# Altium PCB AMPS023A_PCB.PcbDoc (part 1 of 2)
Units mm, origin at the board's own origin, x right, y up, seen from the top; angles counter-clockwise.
Board outline 85 x 120 mm, 4 copper layers (Top Layer, Signal Layer 1, Signal Layer 2, Bottom Layer), stack 1.567 mm thick; 131 components, 63 nets, 410 pads, 509 vias.
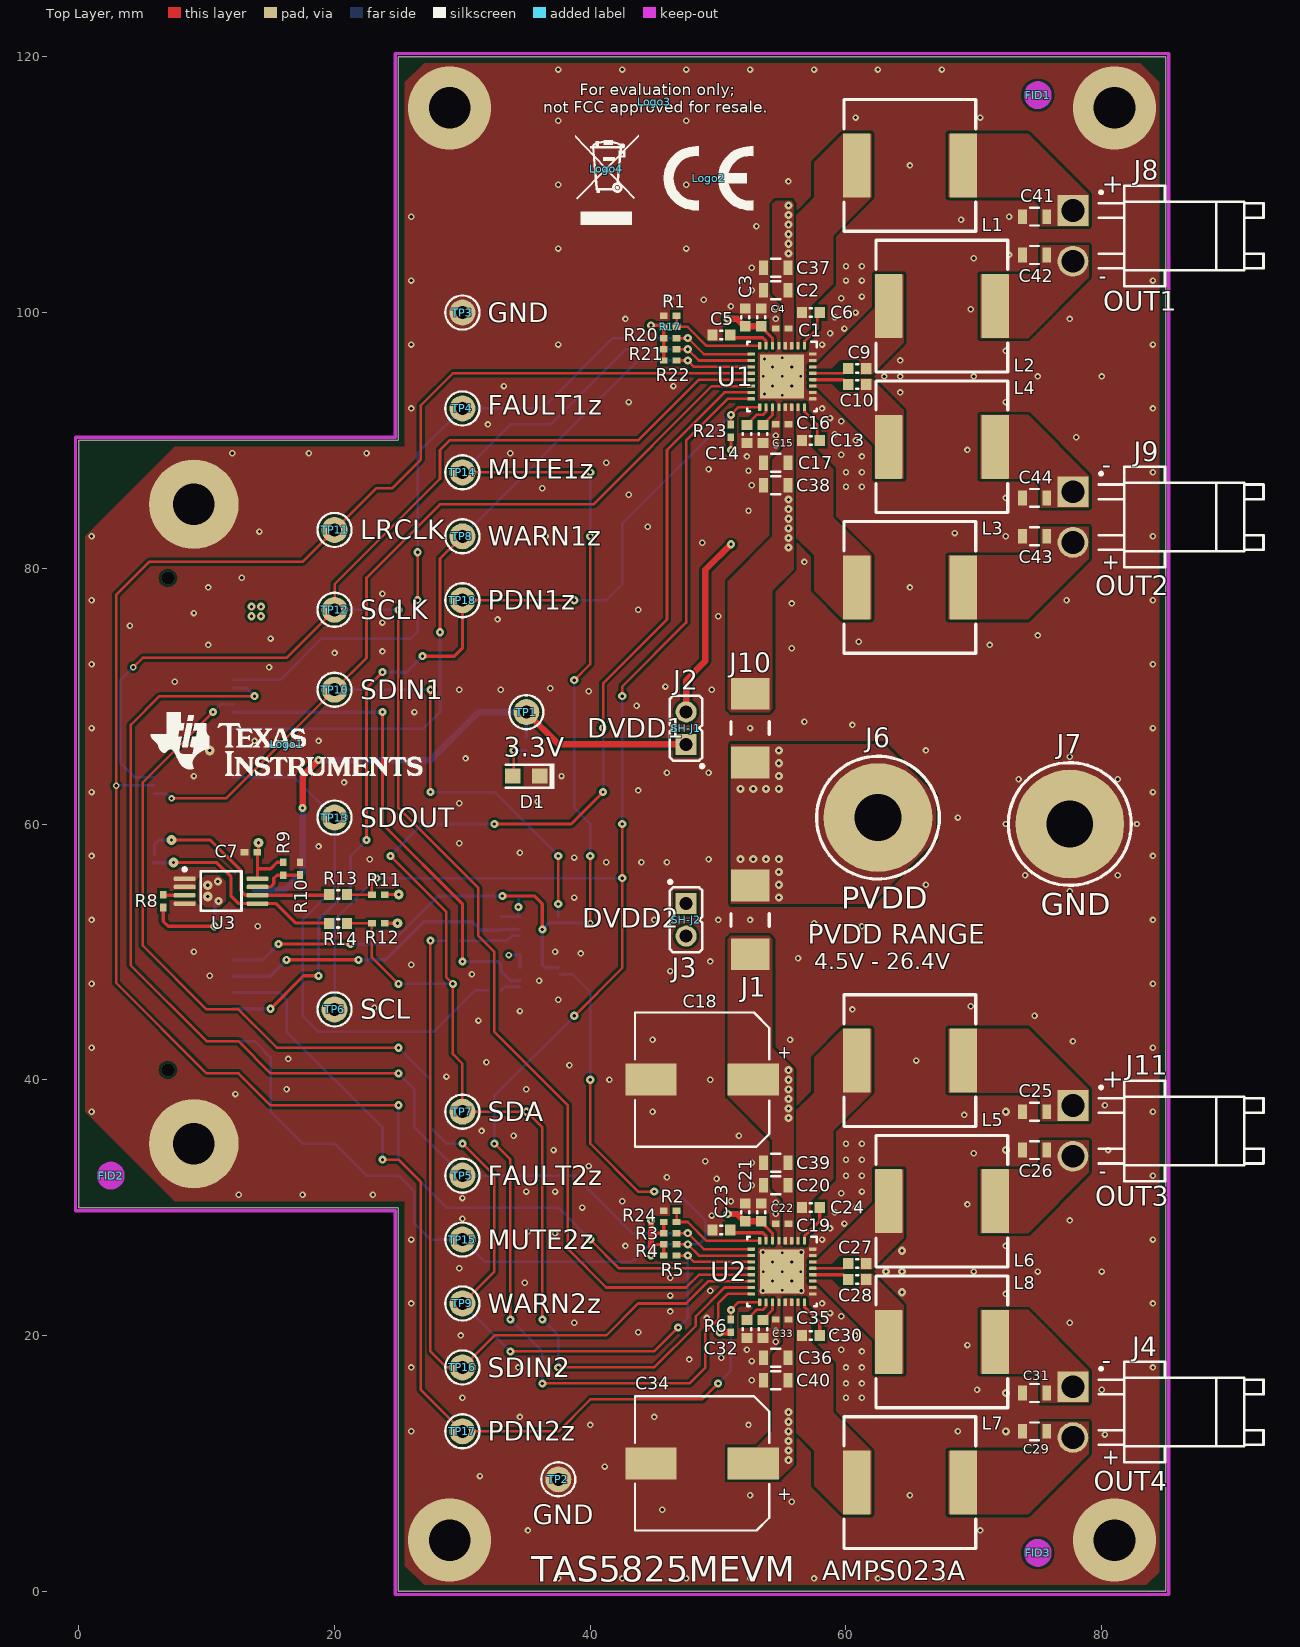
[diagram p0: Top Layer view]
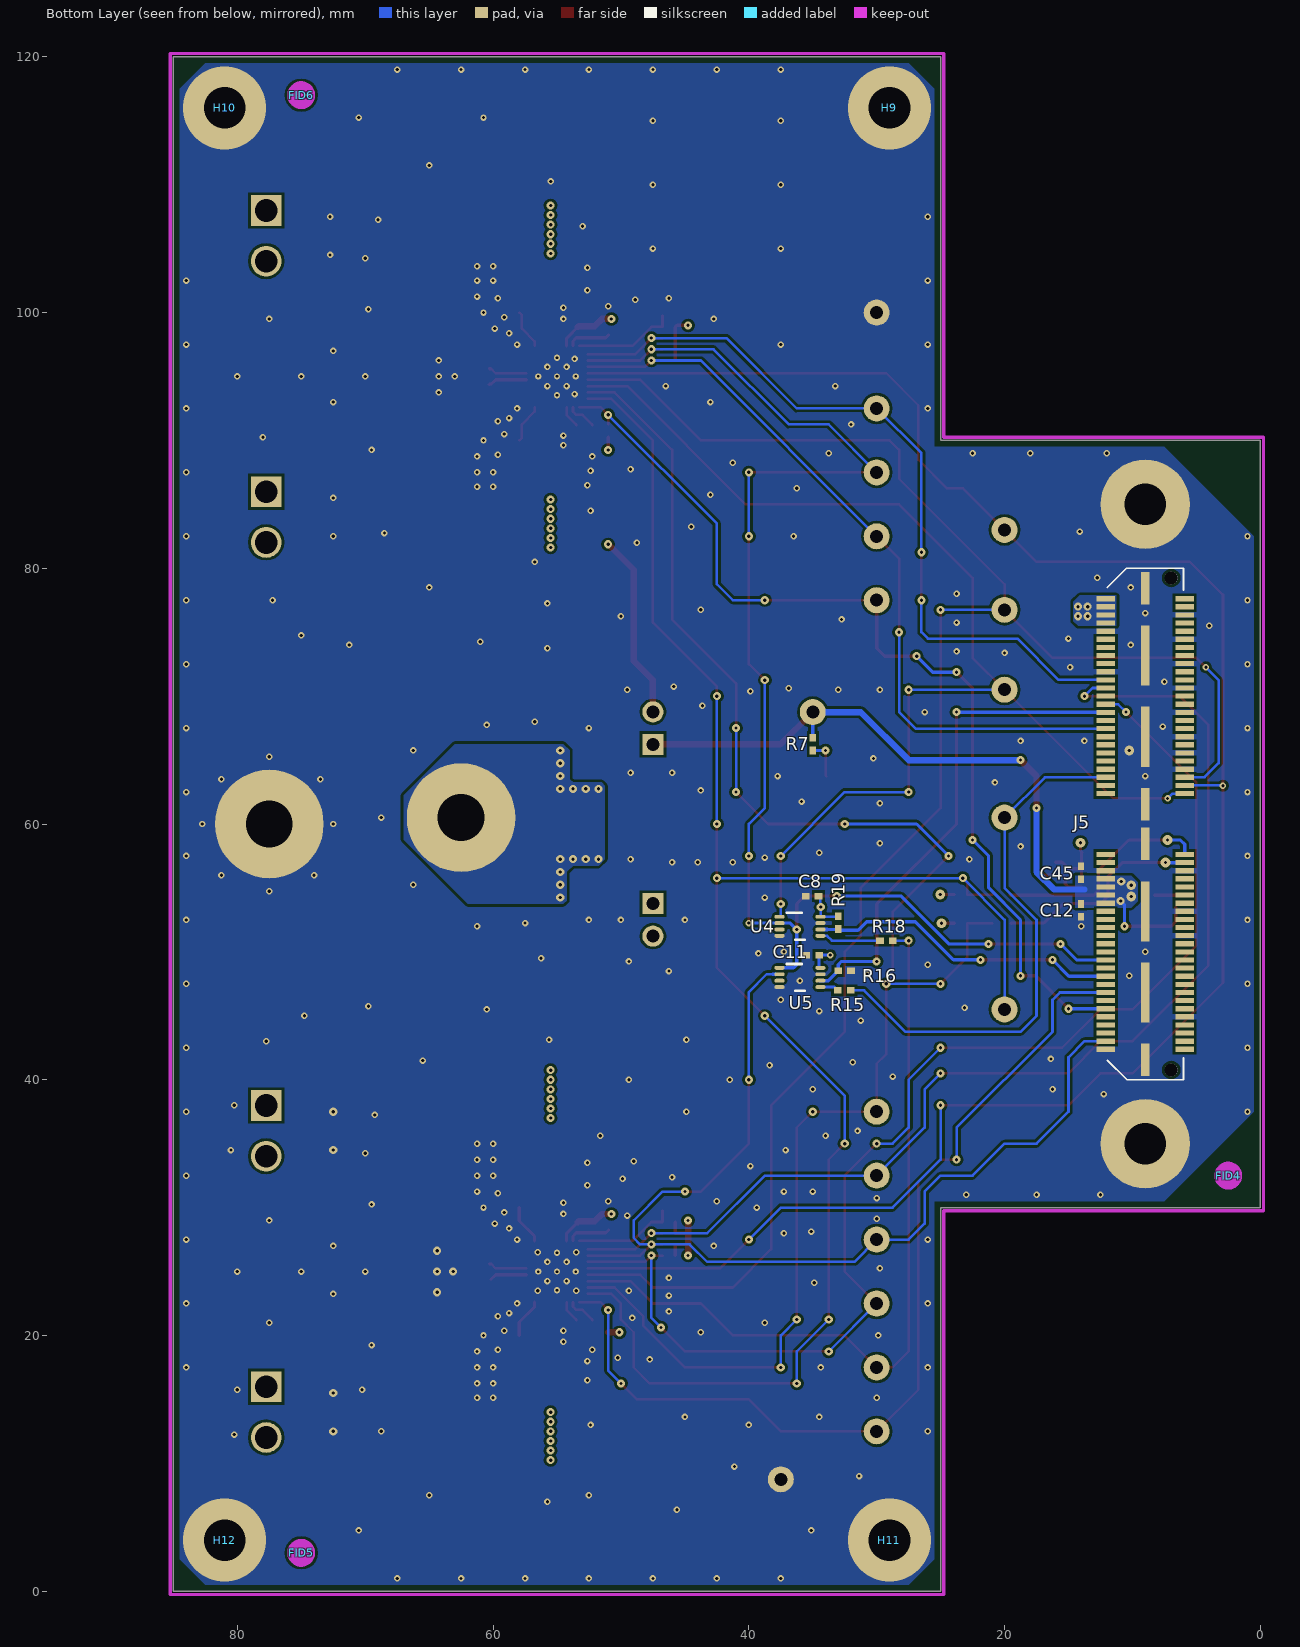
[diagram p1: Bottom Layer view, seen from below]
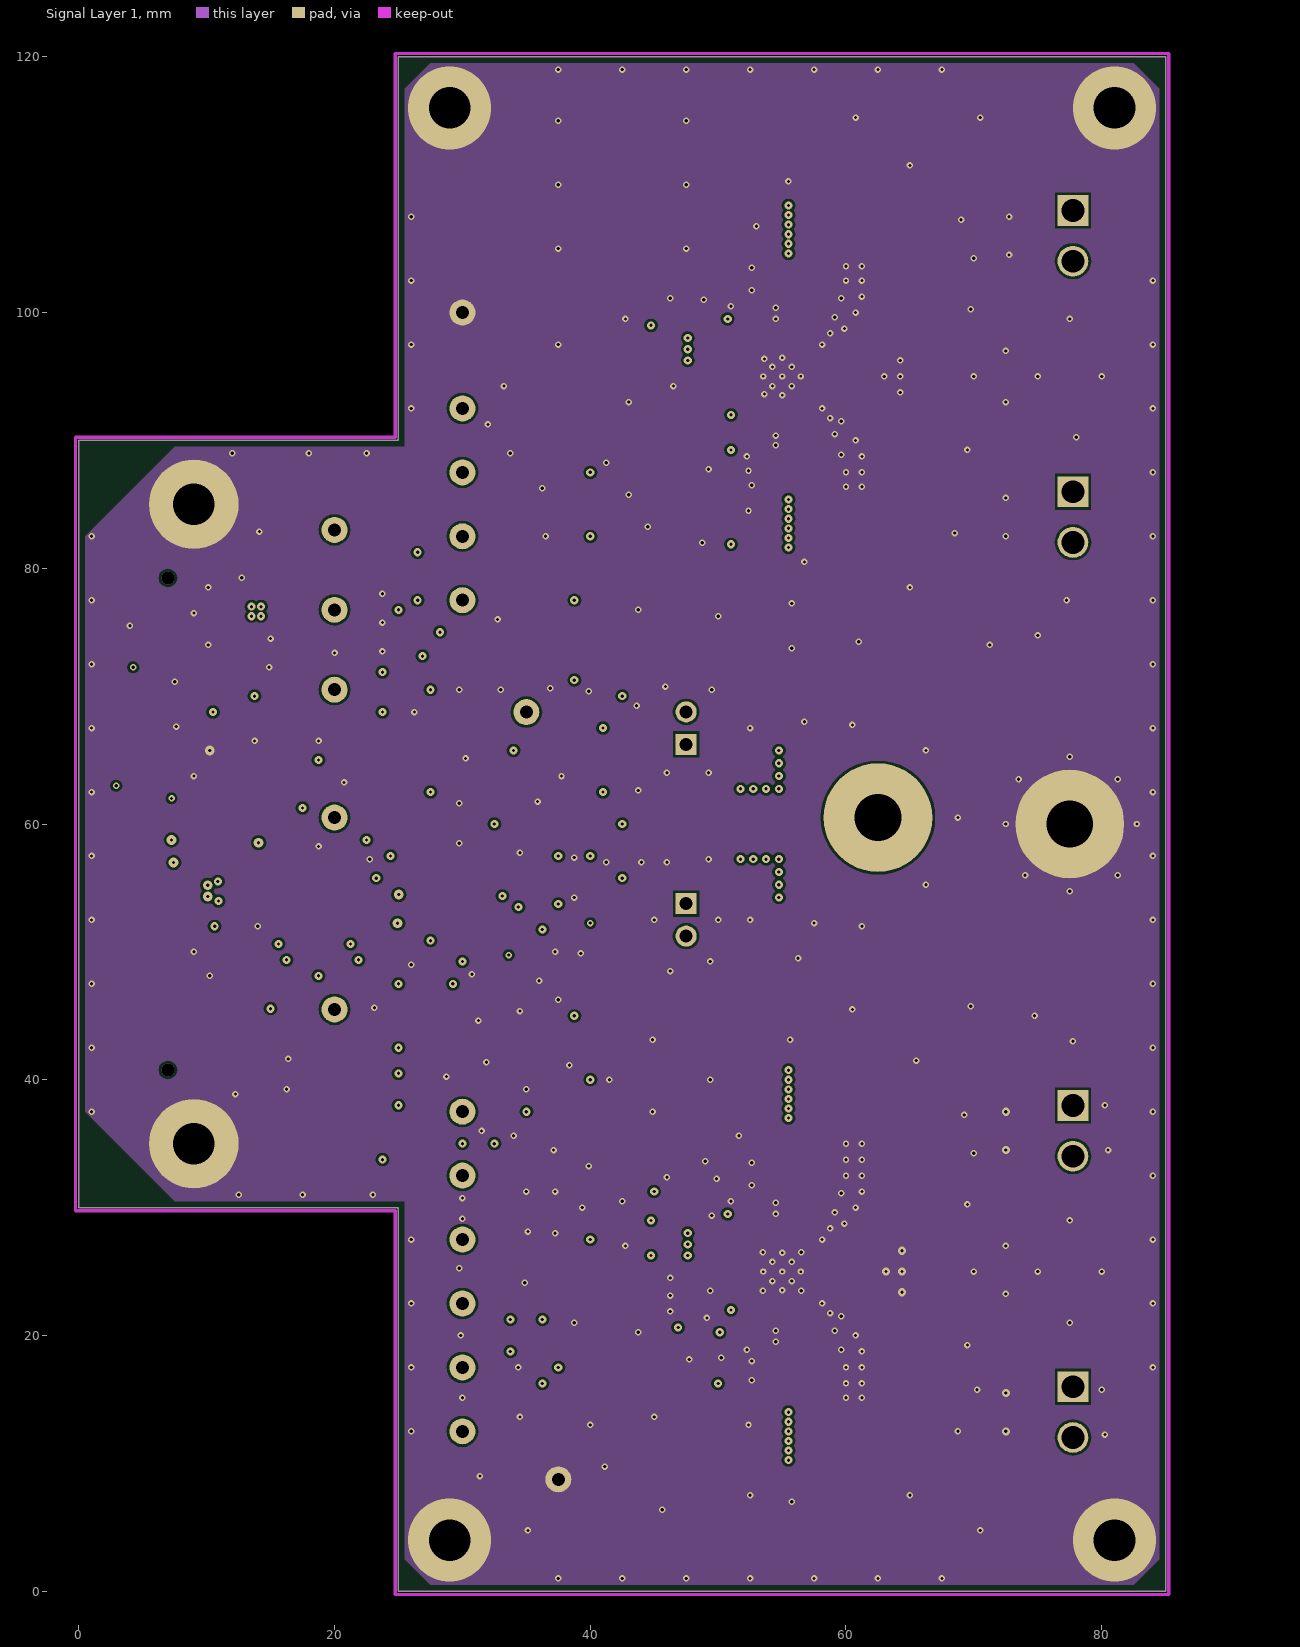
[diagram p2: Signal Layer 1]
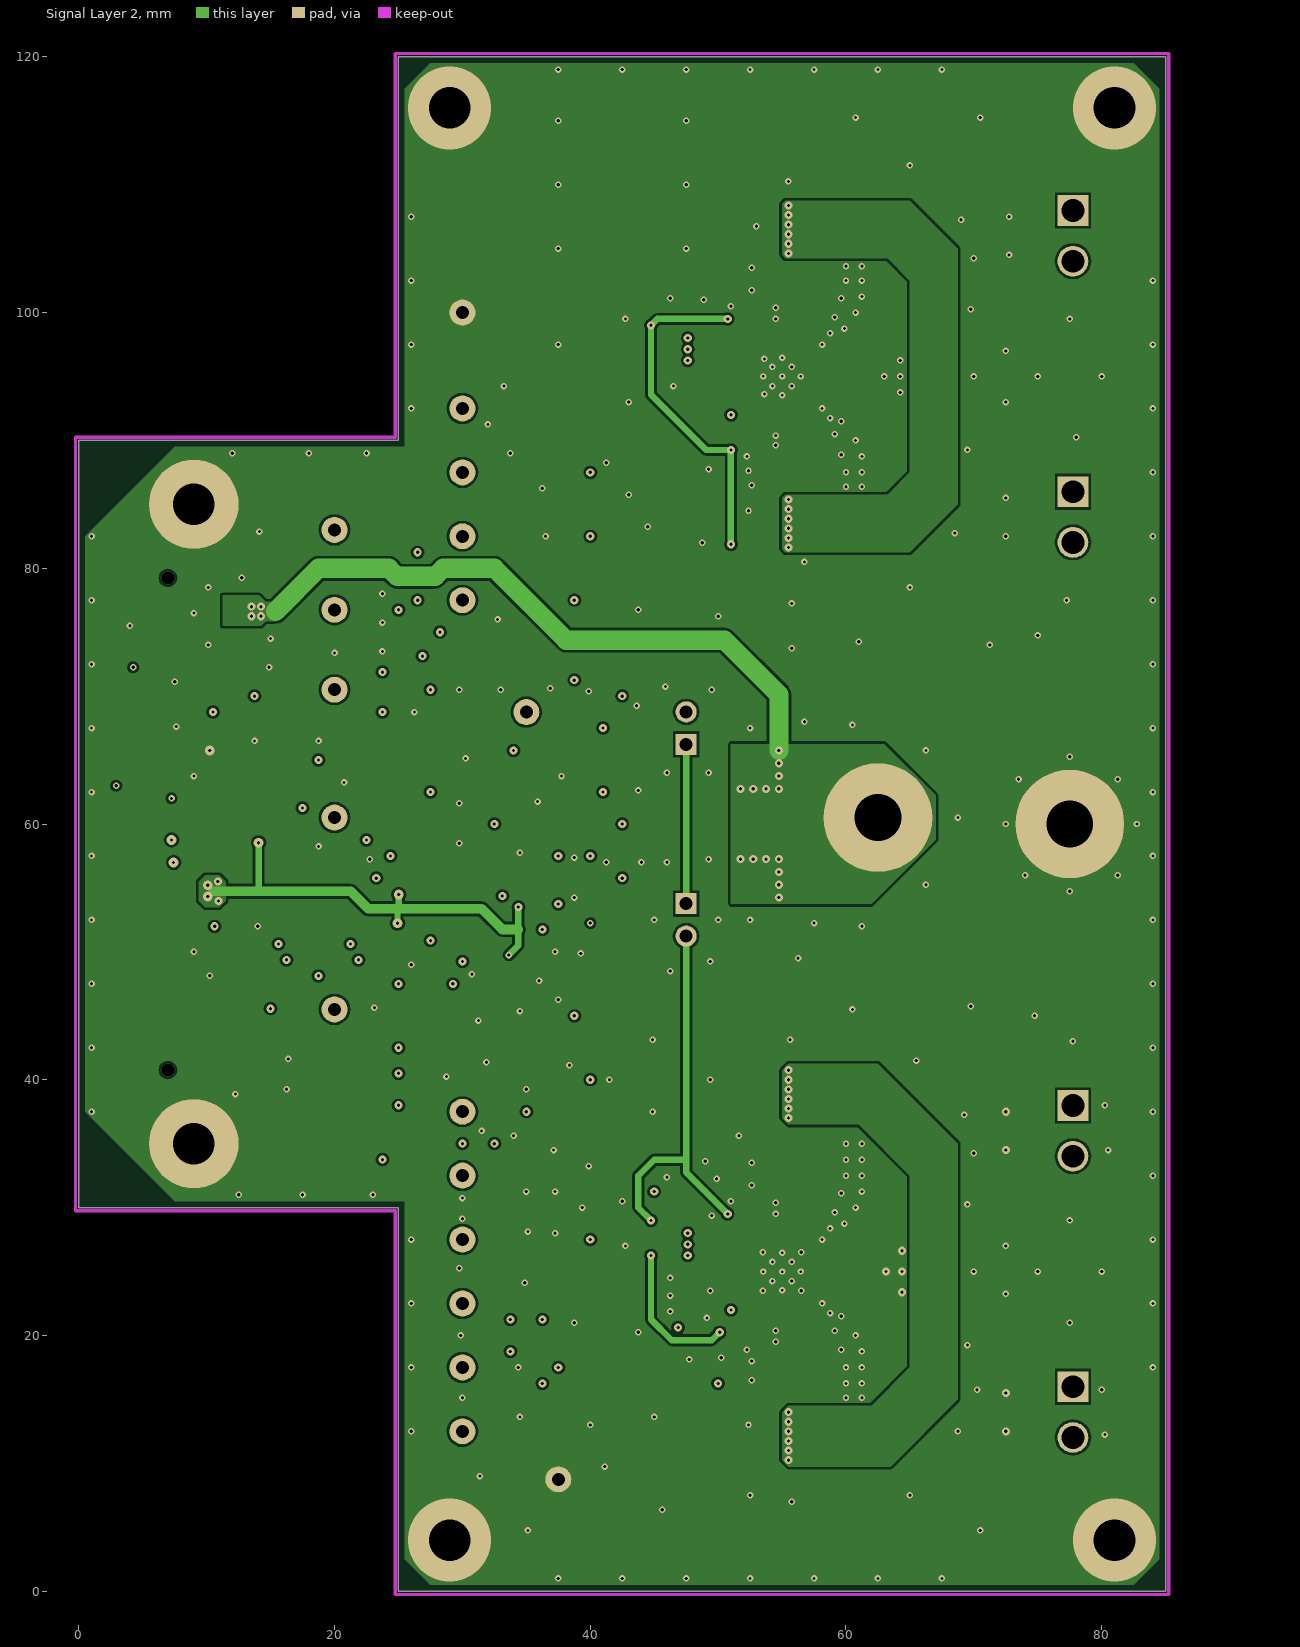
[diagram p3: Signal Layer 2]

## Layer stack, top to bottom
Top Solder: solder mask 0.0102, Solder Resist, Dk 3.5
Top Layer: signal copper 0.0696
Dielectric 1: prepreg 0.2032, FR-4, Dk 4.2
Signal Layer 1: signal copper 0.0356
Dielectric 2: core 0.9505, FR-4, Dk 4.2
Signal Layer 2: signal copper 0.0356
Dielectric 3: prepreg 0.2032, FR-4, Dk 4.2
Bottom Layer: signal copper 0.0696
Bottom Solder: solder mask 0.0102, Solder Resist, Dk 3.5

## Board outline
0,30 25,30 25,0 85,0 85,120 25,120 25,90 0,90

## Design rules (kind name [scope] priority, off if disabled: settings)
AcuteAngle [All] p1: minimum=4.50000000000000E+0001 checktracksonly=FALSE
AssemblyTestPointUsage [All] p1: valid=2
Clearance "Clearance Fiducial LibErrors" [InComponent('FID*')] p1: gap=0.2 ignorepadtopadclearanceinfootprint=TRUE except(0: Arc-SMDPad Arc-Hole Track-SMDPad Track-Hole SMDPad-Hole THPad-Hole Via-Hole Fill-Hole Poly-Hole Region-Hole Text-Hole)
Clearance Clearance_BoardEdge [OnCopper and Not InComponentClass('Logo') and not InComponentClass('FiducialMark') and not InRegion(1000,500,4000,800) and Not IsKeepout vs IsKeepOut] p2: gap=0.2 ignorepadtopadclearanceinfootprint=FALSE except(0: Arc-Hole Track-Hole SMDPad-Hole THPad-Hole Via-Hole Fill-Hole Poly-Hole Region-Hole Text-Hole)
Clearance Clearance_BoardEdge_Poly [OnCopper and InPoly vs IsKeepOut] p3: gap=0.2 ignorepadtopadclearanceinfootprint=FALSE except(0: Arc-Hole Track-Hole SMDPad-Hole THPad-Hole Via-Hole Fill-Hole Poly-Hole Region-Hole Text-Hole)
Clearance Clearance_BoardEdge_MountingHoles [OnCopper and InComponentClass('Mounting Hardware') vs IsKeepOut] p4: gap=0.2 ignorepadtopadclearanceinfootprint=FALSE except(0: Arc-Hole Track-Hole SMDPad-Hole THPad-Hole Via-Hole Fill-Hole Poly-Hole Region-Hole Text-Hole)
Clearance "Poly Clearance 3.3V" [InNamedPolygon('+3.3V_L04_P006')] p5: gap=0.2 ignorepadtopadclearanceinfootprint=FALSE except(0: Arc-Hole Track-Hole SMDPad-Hole THPad-Hole Via-Hole Fill-Hole Poly-Hole Region-Hole Text-Hole)
Clearance "Poly Clearance Outputs" [(InNet('SPK1_OUTA+') AND InNet('SPK1_OUTA-') AND InNet('SPK1_OUTB+') AND InNet('SPK1_OUTB-') AND InNet('SPK2_OUTA+') AND InNet('SPK2_OUTA-') AND InNet('SPK2_OUTB+') AND InNet('SPK2_OUTB-')) vs (InComponent('UD1') AND InComponent('UD2'))] p6: gap=0.2 ignorepadtopadclearanceinfootprint=FALSE except(0: Arc-Hole Track-Hole SMDPad-Hole THPad-Hole Via-Hole Fill-Hole Poly-Hole Region-Hole Text-Hole)
Clearance "Poly Clearance PVDD" [All] p7: gap=0.2 ignorepadtopadclearanceinfootprint=FALSE except(0: Arc-Hole Track-Hole SMDPad-Hole THPad-Hole Via-Hole Fill-Hole Poly-Hole Region-Hole Text-Hole)
Clearance Clearance_Keepouts [((IsTrack Or IsArc) And Not InPoly) And IsFree and IsKeepOut vs ((IsTrack Or IsArc) And Not InPoly) And IsFree and IsKeepOut] p8: gap=0 ignorepadtopadclearanceinfootprint=FALSE
Clearance Clearance_Poly [InPolygon] p9: gap=0.25 ignorepadtopadclearanceinfootprint=FALSE except(0: Arc-Hole Track-Hole SMDPad-Hole THPad-Hole Via-Hole Fill-Hole Poly-Hole Region-Hole Text-Hole)
Clearance [All] p10: gap=0.2 ignorepadtopadclearanceinfootprint=FALSE except(0: Arc-Hole Track-Hole SMDPad-Hole THPad-Hole Via-Hole Fill-Hole Poly-Hole Region-Hole Text-Hole)
ComponentClearance "TAS5754 Clearance" [InComponent('U2') vs InComponent('C*')] p1: gap=0.251 collisioncheckmode=3 verticalgap=0 showdistances=FALSE
ComponentClearance ComponentClearance_MountingHoles_FiducialMarks [InComponentClass('Mounting Holes') vs InComponentClass('FiducialMark')] p2: gap=1.27 collisioncheckmode=3 verticalgap=0.254 showdistances=FALSE
ComponentClearance ComponentClearance_Shunt [InComponentClass('Header') vs InComponentClass('Shunt')] p3: gap=0 collisioncheckmode=3 verticalgap=0 showdistances=FALSE
ComponentClearance ComponentClearance_Logo [InComponentClass('Logo')] p4: gap=0 collisioncheckmode=3 verticalgap=0 showdistances=FALSE
ComponentClearance ComponentClearance_ScrewToNut [(HasFootprint('NY PMS 440 0025 PH')) vs (HasFootprint('Keystone_1902C'))] p5: gap=0 collisioncheckmode=3 verticalgap=0 showdistances=FALSE
ComponentClearance ComponentClearance_MountingHoles [InComponentClass('Mounting Holes')] p6: gap=6.35 collisioncheckmode=3 verticalgap=2540 showdistances=FALSE
ComponentClearance ComponentClearance_SmallPassives [HasFootprint('0201*') or HasFootprint('0402*') or HasFootprint('0508') or HasFootprint('0603*') or HasFootprint('0612') or HasFootprint('0805*') or HasFootprint('0815*') or HasFootprint('0830*') or HasFootprint('1206*') or HasFootprint('1210*') or HasFootprint('1808*') or HasFootprint('1812*') or HasFootprint('1825*') or HasFootprint('2010*') or HasFootprint('2220*') or HasFootprint('2225*') or HasFootprint('2512*') or HasFootprint('2728*') or HasFootprint('3518*') or HasFootprint('DCU*') or HasFootprint('DEM*') or HasFootprint('HAR*') or HasFootprint('IND*') or HasFootprint('NFZ*') or HasFootprint('RHB*') or HasFootprint('SM*') vs HasFootprint('0201*') or HasFootprint('0402*') or HasFootprint('0508') or HasFootprint('0603*') or HasFootprint('0612') or HasFootprint('0805*') or HasFootprint('0815*') or HasFootprint('0830*') or HasFootprint('1206*') or HasFootprint('1210*') or HasFootprint('1808*') or HasFootprint('1812*') or HasFootprint('1825*') or HasFootprint('2010*') or HasFootprint('2220*') or HasFootprint('2225*') or HasFootprint('2512*') or HasFootprint('2728*') or HasFootprint('3518*') or HasFootprint('DCU*') or HasFootprint('DEM*') or HasFootprint('HAR*') or HasFootprint('IND*') or HasFootprint('NFZ*') or HasFootprint('RHB*') or HasFootprint('SM*')] p7: gap=0.2 collisioncheckmode=3 verticalgap=0 showdistances=FALSE
ComponentClearance ComponentClearance_THtoSMT [IsThruComponent vs IsSMTComponent] p8: gap=0 collisioncheckmode=3 verticalgap=0 showdistances=FALSE
ComponentClearance ComponentClearance_THtoTH [IsThruComponent vs IsThruComponent] p9: gap=0.25 collisioncheckmode=3 verticalgap=0 showdistances=FALSE
ComponentClearance [All] p10: gap=1.016 collisioncheckmode=3 verticalgap=0.254 showdistances=FALSE
DiffPairsRouting [All] p1: maxlimit=2.54 minlimit=0.254 mostfreqgap=0.254 toplayer_minwidth=0.381 toplayer_maxwidth=0.381 toplayer_prefwidth=0.381 midlayer1_minwidth=0.381 midlayer1_maxwidth=0.381 midlayer1_prefwidth=0.381 midlayer2_minwidth=0.381 midlayer2_maxwidth=0.381 midlayer2_prefwidth=0.381 bottomlayer_minwidth=0.381 bottomlayer_maxwidth=0.381 bottomlayer_prefwidth=0.381 maxuncoupledlength=25.4
FabricationTestPointUsage TestPointUsage [All] p1: valid=2 allowmultiple=FALSE
FabricationTestpoint Testpoint [All] p1: side=3 testpointundercomponent=TRUE minsize=1.016 maxsize=2.54 preferedsize=1.524 minholesize=0 maxholesize=1.016 preferedholesize=0.813 testpointgrid=0.025 allowsidetop=TRUE allowsidebottom=TRUE usegrid=TRUE gridtolerance=0
FanoutControl Fanout_LCC [IsLCC] p1: bgadir=Out bgaviamode=Centered fanoutstyle=Auto fanoutdirection=Alternating viagrid=0.025 // Fanout_LCC (Default Rule)
FanoutControl Fanout_BGA [IsBGA] p2: bgadir=Out bgaviamode=Centered fanoutstyle=Auto fanoutdirection=Alternating viagrid=0.025 // Fanout_BGA (Default Rule)
FanoutControl Fanout_Default [All] p4: bgadir=Out bgaviamode=Centered fanoutstyle=Auto fanoutdirection=Alternating viagrid=0.025 // Fanout_Default (Default Rule)
FanoutControl Fanout_Small [(CompPinCount < 5)] p5: bgadir=Out bgaviamode=Centered fanoutstyle=Auto fanoutdirection=OutThenIn viagrid=0.025 // Fanout_Small (Default Rule)
Height [All] p1: minheight=0 maxheight=40 prefheight=25
HoleSize [All] p1: absolutevalues=TRUE maxlimit=3.81 minlimit=0.191 maxpercent=80.000 minpercent=20.000
HoleToHoleClearance "Hole 2 Hole For Hardware" [(InComponentClass('Screw') OR InComponentClass('Standoff') OR InComponentClass('Washer')) vs (InComponentClass('Screw') OR InComponentClass('Standoff') OR InComponentClass('Washer'))] p1: gap=0 allowstackedmicrovias=TRUE
HoleToHoleClearance [All] p2: gap=0.254 allowstackedmicrovias=TRUE
MinimumAnnularRing MinimumAnnularRing_ThermalPadVias [IsVia and InAnyComponent] p1: minimumring=0.15
MinimumAnnularRing [All] p2: minimumring=0.127
MinimumSolderMaskSliver "MinSolderMaskSliver LibErrors" [(HasFootprint('DB*') or HasFootprint('DC*'))] p1: minsoldermaskwidth=0.089
MinimumSolderMaskSliver MinimumSolderMaskSliver_Logo [InComponentClass('Logo') vs InComponentClass('Logo')] p2: minsoldermaskwidth=0.018
MinimumSolderMaskSliver [All] p3: minsoldermaskwidth=0.127
PlaneConnect [All] p1: planeconnectstyle=Relief reliefexpansion=0.254 reliefentries=4 reliefconductorwidth=0.254 reliefairgap=0.254
PolygonConnect PreFlood [All] p1: connectstyle=Direct reliefconductorwidth=0.254 reliefentries=4 polygonreliefangle="90 Angle" airgapwidth=0.254
PolygonConnect "Narrow Thermals" [(InComponent('C*') OR InComponent('D*') OR InComponent('J*') OR InComponent('R*') OR InComponent('S*') OR InComponent('TP*') OR InComponent('U*')) vs InNet('GND')] p2: connectstyle=Relief reliefconductorwidth=0.2 reliefentries=4 polygonreliefangle="90 Angle" airgapwidth=0.2
PolygonConnect "Wide Thermals" [(InComponent('C1') OR InComponent('C3') OR InComponent('C5') OR InComponent('C6') OR InComponent('C137')) vs InNet('GND')] p3: connectstyle=Relief reliefconductorwidth=0.25 reliefentries=4 polygonreliefangle="90 Angle" airgapwidth=1
PolygonConnect "PostFlood GND" [(InComponent('C*') OR InComponent('J2') OR InComponent('J6') OR InComponent('J7') OR InComponent('J8') OR InComponent('U1') OR InComponent('U2')) vs InNet('GND')] p4: connectstyle=Direct reliefconductorwidth=0.254 reliefentries=4 polygonreliefangle="90 Angle" airgapwidth=0.254
PolygonConnect [All] p5: connectstyle=Relief reliefconductorwidth=0.25 reliefentries=4 polygonreliefangle="90 Angle" airgapwidth=0.75
RoutingVias ThermalPadVias [IsVia and InAnyComponent] p1: holewidth=0.2 width=0.5 viastyle="Through Hole" minholewidth=0.2 minwidth=0.5 maxholewidth=0.33 maxwidth=0.6
RoutingVias [All] p2: holewidth=0.203 width=0.711 viastyle="Through Hole" minholewidth=0.203 minwidth=0.457 maxholewidth=3.25 maxwidth=7
SilkToBoardRegionClearance [Not ((IsComment or IsDesignator) And (Hide <> 'False')) and not InRegion(1000,500,4000,800)] p1:
SilkToSilkClearance SilkToSilkClearance_Pb-FreeLogo [(HasFootprint('Pb-Free_Overlay_Medium') OR HasFootprint('Pb-Free_Overlay_Small')) vs (HasFootprint('Pb-Free_Overlay_Medium') OR HasFootprint('Pb-Free_Overlay_Small'))] p1: silktosilkclearance=0
SilkToSilkClearance [All] p2: silktosilkclearance=0.127
SilkToSolderMaskClearance "SilkToMask LibErrors" [HasFootprint('LTST*') or HasFootprint('DCU*')] p1: minsilkscreentomaskgap=0.076 clearancetoexposedcopper=FALSE
SilkToSolderMaskClearance SilkToComponentPadClearance [(IsPad or IsFill or IsRegion) and InAnycomponent] p2: minsilkscreentomaskgap=0.127 clearancetoexposedcopper=TRUE
SilkToSolderMaskClearance "Silk to Solder Mask Opening" [All] p3: minsilkscreentomaskgap=0.019 clearancetoexposedcopper=FALSE
SolderMaskExpansion [All] p1: expansion=0.05
Width [All] p1: maxlimit=5 minlimit=0.15 preferedwidth=0.25 checkconnectedcopper=TRUE
13 further rules are at their usual default settings.

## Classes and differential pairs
component class AssemblyNote: ZZ1 ZZ2 ZZ3
component class FiducialMark: FID1 FID2 FID3 FID4 FID5 FID6
component class AMPS023A_EVM_Hardware: FID1 FID2 FID3 FID4 FID5 FID6 H9 H10 H11 H12 Logo1 Logo2 Logo3 Logo4 SH-J1 SH-J2 ZZ1 ZZ2 ZZ3
component class Logo: Logo1
component class AMPS023A_BTL1: C1 C2 C3 C4 C5 C6 C9 C10 C13 C14 C15 C16 C17 C37 C38 C41 C42 C43 C44 J8 J9 L1 L2 L3 L4 R1 R17 R20 R21 R22 R23 U1
component class AMPS023A_BTL2: C18 C19 C20 C21 C22 C23 C24 C25 C26 C27 C28 C29 C30 C31 C32 C33 C34 C35 C36 C39 C40 J4 J11 L5 L6 L7 L8 R2 R3 R4 R5 R6 R24 U2
component class AMPS023A_PPCMB-IO: C7 C8 C11 C12 C45 D1 J1 J2 J3 J5 J6 J7 J10 R7 R8 R9 R10 R11 R12 R13 R14 R15 R16 R18 R19 R25 R26 R33 R35 R38 R39 R40 TP1 TP2 TP3 TP4 TP5 TP6 TP7 TP8 TP9 TP10 TP11 TP12 TP13 TP14 TP15 TP16 TP17 TP18 U3 U4 U5
component class Header: J2 J3
component class Shunt: SH-J1 SH-J2

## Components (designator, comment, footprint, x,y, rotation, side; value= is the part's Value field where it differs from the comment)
C1 "C1005X7R1H104K050BB" 0402L 55,98.75 r180 top value=0.1uF
C2 "C2012JB1V226M125AC" 0805_KTR 54.5,101.75 r0 top value=22uF
C3 "C0603C475K8PACTU" 0603L 52.125,99.625 r270 top value=4.7uF
C4 "C0603C104K4RACTU" 0603L 53.375,99.625 r90 top value=0.1uF
C5 "C0603C105K4PACTU" 0603L 50.25,98.25 r180 top value=1uF
C6 "C1608X7R1H224K080AB" 0603L 57.25,100 r180 top value=0.22uF
C7 "C1005X7R1H104K050BB" 0402L 13.462,57.784 r180 top value=0.1uF
C8 "C1005X7R1H104K050BB" 0402L 35.052,54.356 r180 bottom value=0.1uF
C9 "C1608X7R1H224K080AB" 0603L 60.875,95.625 r0 top value=0.22uF
C10 "C1608X7R1H224K080AB" 0603L 60.875,94.375 r0 top value=0.22uF
C11 "C1005X7R1H104K050BB" 0402L 35,49.75 r180 bottom value=0.1uF
C12 "C1005X7R1H104K050BB" 0402L 14.021,53.237 r90 bottom value=0.1uF
C13 "C1608X7R1H224K080AB" 0603L 57.25,90 r180 top value=0.22uF
C14 "C0603C105K4PACTU" 0603L 52.25,90.5 r270 top value=1uF
C15 "C0603C105K4PACTU" 0603L 53.5,90.5 r270 top value=1uF
C16 "C1005X7R1H104K050BB" 0402L 55,91.25 r180 top value=0.1uF
C17 "C2012JB1V226M125AC" 0805_KTR 54.5,88.25 r0 top value=22uF
C18 "+" SM_RADIAL_10BMM 48.75,40 r180 top value=390uF
C19 "C1005X7R1H104K050BB" 0402L 55,28.75 r180 top value=0.1uF
C20 "C2012JB1V226M125AC" 0805_KTR 54.5,31.75 r0 top value=22uF
C21 "C0603C475K8PACTU" 0603L 52.125,29.625 r270 top value=4.7uF
C22 "C0603C104K4RACTU" 0603L 53.375,29.625 r90 top value=0.1uF
C23 "C0603C105K4PACTU" 0603L 50.25,28.25 r180 top value=1uF
C24 "C1608X7R1H224K080AB" 0603L 57.25,30 r180 top value=0.22uF
C25 "C0805C684K5RACTU" 0805_KTR 74.75,37.5 r180 top value=0.68uF
C26 "C0805C684K5RACTU" 0805_KTR 74.75,34.5 r180 top value=0.68uF
C27 "C1608X7R1H224K080AB" 0603L 60.875,25.625 r0 top value=0.22uF
C28 "C1608X7R1H224K080AB" 0603L 60.875,24.375 r0 top value=0.22uF
C29 "C0805C684K5RACTU" 0805_KTR 74.75,12.5 r180 top value=0.68uF
C30 "C1608X7R1H224K080AB" 0603L 57.25,20 r180 top value=0.22uF
C31 "C0805C684K5RACTU" 0805_KTR 74.75,15.5 r180 top value=0.68uF
C32 "C0603C105K4PACTU" 0603L 52.25,20.5 r270 top value=1uF
C33 "C0603C105K4PACTU" 0603L 53.5,20.5 r270 top value=1uF
C34 "+" SM_RADIAL_10BMM 48.75,10 r180 top value=390uF
C35 "C1005X7R1H104K050BB" 0402L 55,21.25 r180 top value=0.1uF
C36 "C2012JB1V226M125AC" 0805_KTR 54.5,18.25 r0 top value=22uF
C37 "C2012JB1V226M125AC" 0805_KTR 54.5,103.5 r0 top value=22uF
C38 "C2012JB1V226M125AC" 0805_KTR 54.5,86.5 r0 top value=22uF
C39 "C2012JB1V226M125AC" 0805_KTR 54.5,33.5 r0 top value=22uF
C40 "C2012JB1V226M125AC" 0805_KTR 54.5,16.5 r0 top value=22uF
C41 "C0805C684K5RACTU" 0805_KTR 74.75,107.5 r180 top value=0.68uF
C42 "C0805C684K5RACTU" 0805_KTR 74.75,104.5 r180 top value=0.68uF
C43 "C0805C684K5RACTU" 0805_KTR 74.75,82.5 r180 top value=0.68uF
C44 "C0805C684K5RACTU" 0805_KTR 74.75,85.5 r180 top value=0.68uF
C45 "C1005X7R1H104K050BB" 0402L 14.021,56.184 r270 bottom value=0.1uF
D1 "3.3V" LTST-C170KGKT_Green 35,63.75 r0 top value=Green
FID1 "DNP" Fiducial6.4-20 75,117 r0 top
FID2 "DNP" Fiducial6.4-20 2.5,32.5 r0 top
FID3 "DNP" Fiducial6.4-20 75,3 r0 top
FID4 "DNP" Fiducial6.4-20 2.5,32.5 r180 bottom
FID5 "DNP" Fiducial6.4-20 75,3 r180 bottom
FID6 "DNP" Fiducial6.4-20 75,117 r180 bottom
H9 "Standoff, M3x30mm" Harwin_R30-1003002 29,116 r180 bottom
H10 "Standoff, M3x30mm" Harwin_R30-1003002 81,116 r180 bottom
H11 "Standoff, M3x30mm" Harwin_R30-1003002 29,4 r180 bottom
H12 "Standoff, M3x30mm" Harwin_R30-1003002 81,4 r180 bottom
J1 "" HARWIN_S1911-46R 52.5,52.5 r90 top
J2 "DVDD1" Sullins_PBC02SAAN 47.5,67.5 r180 top
J3 "DVDD2" Sullins_PBC02SAAN 47.5,52.5 r0 top
J4 "OUT4" JST_B2PS-VH 77.75,14 r0 top
J5 "QTS-050-01-F-D-A" CONN_QTS-050-01-F-D-A 9,60 r270 bottom locked
J6 "PVDD" Keystone_7006 62.5,60.5 r0 top locked
J7 "GND" Keystone_7007 77.5,60 r0 top
J8 "OUT1" JST_B2PS-VH 77.75,106 r0 top
J9 "OUT2" JST_B2PS-VH 77.75,84 r0 top
J10 "" HARWIN_S1911-46R 52.5,67.5 r270 top
J11 "OUT3" JST_B2PS-VH 77.75,36 r0 top
L1 "1274AS-H-100M=P3" DEM10050C 65,111.5 r0 top value=10uH
L2 "1274AS-H-100M=P3" DEM10050C 67.5,100.5 r0 top value=10uH
L3 "1274AS-H-100M=P3" DEM10050C 65,78.5 r0 top value=10uH
L4 "1274AS-H-100M=P3" DEM10050C 67.5,89.5 r0 top value=10uH
L5 "1274AS-H-100M=P3" DEM10050C 65,41.5 r0 top locked value=10uH
L6 "1274AS-H-100M=P3" DEM10050C 67.5,30.5 r0 top locked value=10uH
L7 "1274AS-H-100M=P3" DEM10050C 65,8.5 r0 top value=10uH
L8 "1274AS-H-100M=P3" DEM10050C 67.5,19.5 r0 top value=10uH
Logo1 "Texas Instruments" TI_Stacked_Overlay_Small 16.25,66.25 r0 top
Logo2 "CE Mark" CE_Mark_5mm 49.25,110.5 r0 top
Logo3 "FCC disclaimer" FCC_disclaimer_stacked 45,116.5 r0 top
Logo4 "WEEE logo" WEEE_Minimum 41.25,111.25 r0 top
R1 "" 0402L 46.25,99.75 r180 top value=0
R2 "ERA-2AEB102X" 0402L 46.25,29.75 r180 top value=1.00k
R3 "RMCF0402FT10K0" 0402L 46.25,28 r180 top value=10.0k
R4 "RMCF0402FT10K0" 0402L 46.25,27.125 r180 top value=10.0k
R5 "RMCF0402FT10K0" 0402L 46.25,26.25 r180 top value=10.0k
R6 "RMCF0402FT10K0" 0402L 51,20.75 r270 top value=10.0k
R7 "ERJ-2RKF4700X" 0402L 35,66.25 r90 bottom value=470
R8 "RMCF0402FT10K0" 0402L 6.604,53.974 r270 top value=10.0k
R9 "DNP" 0402L 16,56.5 r270 top value=10.0k
R10 "RMCF0402FT10K0" 0402L 17.297,56.514 r270 top value=10.0k
R11 "RC0402FR-072K2L" 0402L 23.426,54.482 r0 top value=2.20k
R12 "RC0402FR-072K2L" 0402L 23.426,52.232 r0 top value=2.20k
R13 "ERJ-3GEY0R00V" 0603L 20.279,54.482 r180 top value=0
R14 "ERJ-3GEY0R00V" 0603L 20.279,52.232 r180 top value=0
R15 "RC0402FR-0749R9L" 0402L 32.537,46.99 r180 bottom value=49.9
R16 "RMCF0402FT10K0" 0402L 32.512,48.514 r180 bottom value=10.0k
R17 "DNP" 0402L 46.25,98.875 r180 top value=0
R18 "RC0402FR-0749R9L" 0402L 29.235,50.876 r180 bottom value=49.9
R19 "RMCF0402FT10K0" 0402L 33.02,52.283 r270 bottom value=10.0k
R20 "RMCF0402FT10K0" 0402L 46.25,98 r180 top value=10.0k
R21 "RMCF0402FT10K0" 0402L 46.25,97.125 r180 top value=10.0k
R22 "RMCF0402FT10K0" 0402L 46.25,96.25 r180 top value=10.0k
R23 "RMCF0402FT10K0" 0402L 51,90.75 r270 top value=10.0k
R24 "DNP" 0402L 46.25,28.875 r180 top value=0
SH-J1 "SNT-100-BK-G" SNT-100-BK-G 47.5,67.5 r90 top value=1x2
SH-J2 "SNT-100-BK-G" SNT-100-BK-G 47.5,52.5 r90 top value=1x2
TP1 "3.3V" Keystone5000 35,68.75 r90 top
TP2 "GND" Keystone5001 37.5,8.75 r90 top
TP3 "GND" Keystone5001 30,100 r90 top
TP4 "FAULT1z" Keystone5003 30,92.5 r90 top
TP5 "FAULT2z" Keystone5003 30,32.5 r90 top
TP6 "SCL" Keystone5003 20,45.5 r0 top
TP7 "SDA" Keystone5003 30,37.5 r0 top
TP8 "WARN1z" Keystone5003 30,82.5 r90 top
TP9 "WARN2z" Keystone5003 30,22.5 r90 top
TP10 "SDIN1" Keystone5003 20,70.5 r90 top
TP11 "LRCLK" Keystone5003 20,83 r90 top
TP12 "SCLK" Keystone5003 20,76.75 r90 top
TP13 "SDOUT" Keystone5003 20,60.5 r90 top
TP14 "MUTE1z" Keystone5003 30,87.5 r90 top
TP15 "MUTE2z" Keystone5003 30,27.5 r90 top
TP16 "SDIN2" Keystone5003 30,17.5 r90 top
TP17 "PDN2z" Keystone5003 30,12.5 r90 top
TP18 "PDN1z" Keystone5003 30,77.5 r90 top
U1 "TAS5825MRHBR" RHB0032N 55,95 r270 top locked
U2 "TAS5825MRHBR" RHB0032N 55,25 r270 top locked
U3 "24LC512-I/ST" TSSOP-8 11.125,54.75 r0 top
U4 "LVC2G157" DCU0008A_N 36,52 r180 bottom
U5 "LVC2G157" DCU0008A_N 36,48 r180 bottom
ZZ1 "These assemblies are ESD sensitive, ESD precautions shall be observed." AssemblyNote 3,129 r0 top
ZZ2 "These assemblies must be clean and free from flux and all contaminants. Use of no clean flux is not acceptable." AssemblyNote 3,126 r0 top
ZZ3 "These assemblies must comply with workmanship standards IPC-A-610 Class 2, unless otherwise specified." AssemblyNote 3,123 r0 top

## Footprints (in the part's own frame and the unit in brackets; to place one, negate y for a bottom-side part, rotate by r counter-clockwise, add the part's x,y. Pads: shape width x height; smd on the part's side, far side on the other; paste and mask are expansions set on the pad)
0402L [mm] "0402 from SM-752 data"
  rect 0.6x0.5 smd: 1(-0.5,0) 2(0.5,0)
  body extent -0.55,-0.3 0.55,0.3, height 0.6
0603L [mm] "0603 from SM-752 data"
  rect 0.8x0.85 smd: 1(-0.7,0) 2(0.7,0)
  silkscreen extent -0.07,-0.33 0.07,0.33, body extent -0.87,-0.47 0.87,0.47, height 1
0805_KTR [mm] "ROHM"
  rect 0.7x1.15 smd: 1(-0.95,0) 2(0.95,0)
  silkscreen extent -0.35,-0.7 0.35,0.7, body extent -1.05,-0.67 1.05,0.67, height 0.65
AssemblyNote [mm] "Assembly Note"
CE_Mark_5mm [mm] "Minimum text height for CE Mark"
  silkscreen extent -3.5,-2.5 3.5,2.5
CONN_QTS-050-01-F-D-A [mil] "SAMTEC"
  rect 16x57 smd: 1(-693.75,121.5) 2(-693.75,-121.5) 3(-668.75,121.5) 4(-668.75,-121.5) 5(-643.75,121.5) 6(-643.75,-121.5) 7(-618.75,121.5) 8(-618.75,-121.5) 9(-593.75,121.5) 10(-593.75,-121.5) 11(-568.75,121.5) 12(-568.75,-121.5) 13(-543.75,121.5) 14(-543.75,-121.5) 15(-518.75,121.5) 16(-518.75,-121.5) 17(-493.75,121.5) 18(-493.75,-121.5) 19(-468.75,121.5) 20(-468.75,-121.5) 21(-443.75,121.5) 22(-443.75,-121.5) 23(-418.75,121.5) 24(-418.75,-121.5) 25(-393.75,121.5) 26(-393.75,-121.5) 27(-368.75,121.5) 28(-368.75,-121.5) 29(-343.75,121.5) 30(-343.75,-121.5) 31(-318.75,121.5) 32(-318.75,-121.5) 33(-293.75,121.5) 34(-293.75,-121.5) 35(-268.75,121.5) 36(-268.75,-121.5) 37(-243.75,121.5) 38(-243.75,-121.5) 39(-218.75,121.5) 40(-218.75,-121.5) 41(-193.75,121.5) 42(-193.75,-121.5) 43(-168.75,121.5) 44(-168.75,-121.5) 45(-143.75,121.5) 46(-143.75,-121.5) 47(-118.75,121.5) 48(-118.75,-121.5) 49(-93.75,121.5) 50(-93.75,-121.5) 51(93.75,121.5) 52(93.75,-121.5) 53(118.75,121.5) 54(118.75,-121.5) 55(143.75,121.5) 56(143.75,-121.5) 57(168.75,121.5) 58(168.75,-121.5) 59(193.75,121.5) 60(193.75,-121.5) 61(218.75,121.5) 62(218.75,-121.5) 63(243.75,121.5) 64(243.75,-121.5) 65(268.75,121.5) 66(268.75,-121.5) 67(293.75,121.5) 68(293.75,-121.5) 69(318.75,121.5) 70(318.75,-121.5) 71(343.75,121.5) 72(343.75,-121.5) 73(368.75,121.5) 74(368.75,-121.5) 75(393.75,121.5) 76(393.75,-121.5) 77(418.75,121.5) 78(418.75,-121.5) 79(443.75,121.5) 80(443.75,-121.5) 81(468.75,121.5) 82(468.75,-121.5) 83(493.75,121.5) 84(493.75,-121.5) 85(518.75,121.5) 86(518.75,-121.5) 87(543.75,121.5) 88(543.75,-121.5) 89(568.75,121.5) 90(568.75,-121.5) 91(593.75,121.5) 92(593.75,-121.5) 93(618.75,121.5) 94(618.75,-121.5) 95(643.75,121.5) 96(643.75,-121.5) 97(668.75,121.5) 98(668.75,-121.5) 99(693.75,121.5) 100(693.75,-121.5)
  rect 100x25 smd: 101(-726,0) 104(-61.25,0) 105(61.25,0) 108(726.25,0)
  rect 185x25 smd: 102(-518.75,0) 103(-268.75,0) 106(269,0) 107(518.75,0)
  round 39 hole 40 unplated: MH1(-757.5,80) MH2(757.5,80)
  silkscreen extent -788,-117 787,118, body extent -787,-140 788,140, height 166
DCU0008A_N [mm] "TSSOP, 8-Leads, Body 2x2.3mm, Pitch 0.5mm, IPC Medium Density"
  oval 0.8x0.3 smd: 1(-1.6,0.75) 2(-1.6,0.25) 3(-1.6,-0.25) 4(-1.6,-0.75) 5(1.6,-0.75) 6(1.6,-0.25) 7(1.6,0.25) 8(1.6,0.75)
  silkscreen extent -1.05,-1.05 0.38,1.05, body extent -1.56,-1 1.56,1, height 0.9
DEM10050C [mm] "MuRata inductor"
  rrect5% 2.15x5 smd: 1(-4.175,0) 2(4.175,0)
  body extent -5.15,-5.15 5.15,5.15, height 5
FCC_disclaimer_stacked [mm]
Fiducial6.4-20 [mm]
  round 0.635 smd mask+0.683: 1(0,0)
  Top Layer keep-out circle w1.178: c0,0 r0.5
Harwin_R30-1003002 [mm] "Standoff Hex Brass M3"
  body extent -3,-3.46 3,3.46, height 30.02
HARWIN_S1911-46R [mm] "HARWIN"
  rect 2.48x3 smd mask+0.102: 1(-2.69,0) 2(2.69,0)
  silkscreen extent -0.5,-1.5 0.5,1.5, body extent -3.42,-1.25 3.43,1.26, height 0.99
JST_B2PS-VH [mm] "JST Sales America Inc"
  rect 2.4x2.4 hole 1.778: 1(0,1.98)
  round 2.4 hole 1.778: 2(0,-1.98)
  silkscreen extent 2,-3.93 14.9,3.93, body extent -0.57,-3.93 14.9,3.93, height 8.52
Keystone5000 [mil] "For Keystone 500x miniature loop terminals"
  round 80 hole 40: 1(0,0)
  silkscreen extent -52,-52 52,52, body extent -49,-49 49,49, height 182
Keystone5001 [mil] "For Keystone 500x miniature loop terminals"
  round 80 hole 40: 1(0,0)
  silkscreen extent -52,-52 52,52, body extent -49,-49 49,49, height 182
Keystone5003 [mil] "For Keystone 500x miniature loop terminals"
  round 80 hole 40: 1(0,0)
  silkscreen extent -52,-52 52,52, body extent -49,-49 49,49, height 182
Keystone_7006 [mm] "KEYSTONE"
  round 8.5 hole 3.658: 1(0,0)
  silkscreen extent -4.8,-4.8 4.8,4.8, body extent -5.68,-5.69 5.7,5.69, height 26.47
Keystone_7007 [mm] "KEYSTONE"
  round 8.5 hole 3.658: 1(0,0)
  silkscreen extent -4.8,-4.8 4.8,4.8, body extent -5.71,-5.66 5.67,5.72, height 26.48
LTST-C170KGKT_Green [mm] "LITE-ON"
  rect 1.2x1.2 smd: 1(-1.05,0) 2(1.05,0)
  silkscreen extent -1.6,-1 2.2,1, body extent -1.05,-0.67 1.05,0.67, height 1.1
RHB0032N [mm] "QFN, 32-Leads, Body 5x5mm, Pitch 0.5mm, Thermal Pad 3.45x3.45mm"
  rrect40% 0.6x0.25 smd: 1(-2.4,1.75) 2(-2.4,1.25) 3(-2.4,0.75) 4(-2.4,0.25) 5(-2.4,-0.25) 6(-2.4,-0.75) 7(-2.4,-1.25) 8(-2.4,-1.75) 17(2.4,-1.75) 18(2.4,-1.25) 19(2.4,-0.75) 20(2.4,-0.25) 21(2.4,0.25) 22(2.4,0.75) 23(2.4,1.25) 24(2.4,1.75)
  rrect40% 0.25x0.6 smd: 9(-1.75,-2.4) 10(-1.25,-2.4) 11(-0.75,-2.4) 12(-0.25,-2.4) 13(0.25,-2.4) 14(0.75,-2.4) 15(1.25,-2.4) 16(1.75,-2.4) 25(1.75,2.4) 26(1.25,2.4) 27(0.75,2.4) 28(0.25,2.4) 29(-0.25,2.4) 30(-0.75,2.4) 31(-1.25,2.4) 32(-1.75,2.4)
  rrect3% 3.45x3.45 smd paste-1.725: 33(0,0)
  rrect7% 1.49x1.49 on Top Paste: ""(-0.845,0.845) ""(-0.845,-0.845) ""(0.845,0.845) ""(0.845,-0.845)
  silkscreen extent -2.72,-2.73 2.72,2.73, body extent -2.5,-2.5 2.5,2.5, height 0.9
SM_RADIAL_10BMM [mm] "Nichicon 10x10"
  rect 4x2.5 smd: 1(-4,0) 2(4,0)
  silkscreen extent -5.25,-5.25 5.25,5.25, body extent -5.25,-5.25 5.25,5.25, height 10.5
SNT-100-BK-G [mil] "Samtec STEP model"
  round 1 on Mech3: 0(0,0)
  body extent -100,-50 100,50, height 344
Sullins_PBC02SAAN [mm] "Sullins 100mil, 1x2, 230 mil above insulator"
  rect 1.65x1.65 hole 1.016: 1(0,1.27)
  round 1.65 hole 1.016: 2(0,-1.27)
  silkscreen extent -1.37,-2.54 1.27,3.1, body extent -1.27,-2.54 1.27,2.54, height 8.38
TI_Stacked_Overlay_Small [mm]
  silkscreen extent -10.63,-2.49 10.63,2.49
TSSOP-8 [mm] "TSSOP, 8-Leads, Body 3.1x4.5mm (max), Pitch 0.65mm, IPC Medium Density"
  rrect50% 1.7x0.35 smd: 1(-2.85,0.975) 2(-2.85,0.325) 3(-2.85,-0.325) 4(-2.85,-0.975) 5(2.85,-0.975) 6(2.85,-0.325) 7(2.85,0.325) 8(2.85,0.975)
  silkscreen extent -2.97,-1.55 1.6,1.82, body extent -3.2,-1.55 3.2,1.55, height 1.07
WEEE_Minimum [mm] "WEEElie bin"
  silkscreen extent -2.42,-4.38 2.52,2.65

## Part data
C1 C7 C8 C11 C12 C16 C19 C35 C45: library part CMP-0006297-2, "CAP, CERM, 0.1 uF, 50 V, +/- 10%, X7R, 0402", Cap_Case=0402, Manufacturer=TDK, Supplier Part Number 1=445-5932-1-ND, TempCo=X7R, Tolerance_%=10%, Value1="0.039064 ohm", Value2=50V, ValueDisplayed=0.1uF
C2 C17 C20 C36 C37 C38 C39 C40: library part CMP-0007821-1, "CAP, CERM, 22 uF, 35 V, +/- 20%, JB, 0805", Cap_Case=0805, Manufacturer=TDK, Supplier Part Number 1=445-11527-6-ND, TempCo=JB, Tolerance_%=20%, Value1=Unknown, Value2=35V, ValueDisplayed=22uF
C3 C21: library part CMP-0006949-5, "CAP, CERM, 4.7 uF, 10 V, +/- 10%, X5R, 0603", Cap_Case=0603, Manufacturer=Kemet, Supplier Part Number 1=399-5503-1-ND, TempCo=X5R, Tolerance_%=10%, Value1="0.006 ohm", Value2=10V, ValueDisplayed=4.7uF
C4 C22: library part CMP-0006860-5, "CAP, CERM, 0.1 uF, 16 V, +/- 10%, X7R, 0603", Cap_Case=0603, Manufacturer=Kemet, Supplier Part Number 1=399-1096-1-ND, TempCo=X7R, Tolerance_%=10%, Value1=Unknown, Value2=16V, ValueDisplayed=0.1uF
C5 C14 C15 C23 C32 C33: library part CMP-0006868-5, "CAP, CERM, 1 uF, 16 V, +/- 10%, X5R, 0603", Cap_Case=0603, Manufacturer=Kemet, Supplier Part Number 1=399-5090-1-ND, TempCo=X5R, Tolerance_%=10%, Value1=Unknown, Value2=16V, ValueDisplayed=1uF
C6 C9 C10 C13 C24 C27 C28 C30: library part CMP-0007047-4, "CAP, CERM, 0.22 uF, 50 V, +/- 10%, X7R, 0603", Cap_Case=0603, Manufacturer=TDK, Supplier Part Number 1=445-7408-1-ND, TempCo=X7R, Tolerance_%=10%, Value1="0.021699 ohm", Value2=50V, ValueDisplayed=0.22uF
C18 C34: library part CMP-0011092-1, "CAP, AL, 390 uF, 35 V, +/- 20%, 0.08 ohm, SMD", Cap_Case=10x10, Manufacturer=Nichicon, PartNumber=UCL1V391MNL1GS, Supplier Part Number 1=493-3960-1-ND, Tolerance_%=20%, Value1="0.08 ohm", Value2=35V, ValueDisplayed=390uF
C25 C26 C29 C31 C41 C42 C43 C44: library part CMP-0007814-2, "CAP, CERM, 0.68 uF, 50 V, +/- 10%, X7R, 0805", Cap_Case=0805, Manufacturer=Kemet, Supplier Part Number 1=399-8114-6-ND, TempCo=X7R, Tolerance_%=10%, Value1=Unknown, Value2=50V, ValueDisplayed=0.68uF
D1: library part CMP-0002888-1, "LED, Green, SMD", Color=Green, Manufacturer=Lite-On, PartNumber=LTST-C170KGKT, Supplier Part Number 1=160-1414-1-ND, Value1=W, Value2=2V
FID1 FID2 FID3 FID4 FID5 FID6: library part CMP-0077181-1, "Fiducial mark.  There is nothing to buy or mount.", Manufacturer=N/A
H9 H10 H11 H12: library part CMP-0003674-1, "Standoff, HexBrass M3, 30 mm", Manufacturer=Harwin, PartNumber=R30-1003002, Supplier Part Number 1=R30-1003002-ND
J1 J10: library part CMP-0075020-1, "JUMPER TIN SMD", Manufacturer=Harwin, PartNumber=S1911-46R, Supplier Part Number 1=952-1740-1-ND
J2 J3: library part CMP-0054566-1, "Header, 100mil, 2x1, Gold, TH", Color=Black, Current_A=3A, Manufacturer="Sullins Connector Solutions", PartNumber=PBC02SAAN, Supplier Part Number 1=S1011E-02-ND, Voltage_V=1.8kV
J4 J8 J9 J11: library part CMP-0074989-1, "Header (friction lock), 3.96mm, 2x1, Tin, R/A, TH", Manufacturer="JST Manufacturing", PartNumber=B2PS-VH(LF)(SN), Supplier Part Number 1=455-1648-ND
J5: library part CMP-0055971-1, "Connector, 100 Pos. 0.635mm, SMT", Manufacturer=Samtec, Supplier Part Number 1=QTS-050-01-F-D-A-ND
J6: library part CMP-0055127-1, "Binding Post, RED, TH", Manufacturer=Keystone, PartNumber=7006, Shell Color=Red, Supplier Part Number 1=36-7006-ND
J7: library part CMP-0055128-1, "Binding Post, BLACK, TH", Manufacturer=Keystone, PartNumber=7007, ShellColor=Black, Supplier Part Number 1=36-7007-ND
L1 L2 L3 L4 L5 L6 L7 L8: library part CMP-0077807-1, "Inductor, Shielded, Ferrite, 10 µH, 4.4 A, 0.0304 ohm, SMD", Manufacturer=MuRata, PartNumber=1274AS-H-100M{}P3, Supplier Part Number 1=490-10850-1-ND, Value1="0.0304 ohm", Value2=4.4A, ValueDisplayed=10µH
Logo1: library part CMP-0074838-1, "Texas Instrument Corporate Signature"
Logo2: library part CMP-0074844-1
Logo3: library part CMP-0074847-1, "FCC_disclaimer"
Logo4: library part CMP-0074769-1
R1 R17 R24: library part CMP-0026992-2, "RES, 0, 5%, 0.063 W, 0402", Manufacturer=Panasonic, PartNumber=ERJ-2GE0R00X, Power_W=63mW, Supplier Part Number 1=P0.0JCT-ND, TempCo="600 ppm/C", Tolerance_%=5%, Value2=0.063W, Value_Code=0000, ValueDisplayed=0
R2: library part CMP-0026770-1, "RES, 1.00 k, 0.1%, 0.063 W, 0402", Manufacturer=Panasonic, Power_W=63mW, Supplier Part Number 1=P1.0KDCCT-ND, TempCo="25 ppm/C", Tolerance_%=0.1%, Value2=0.063W, Value_Code=1k00, ValueDisplayed=1.00k
R3 R4 R5 R6 R8 R10 R16 R19 R20 R21 R22 R23: library part CMP-0026754-1, "RES, 10.0 k, 1%, 0.063 W, AEC-Q200 Grade 0, 0402", Manufacturer="Stackpole Electronics Inc", Power_W=63mW, Supplier Part Number 1=RMCF0402FT10K0CT-ND, TempCo="100 ppm/C", Tolerance_%=1%, Value2=0.063W, Value_Code=10k0, ValueDisplayed=10.0k
R7: library part CMP-0026699-1, "RES, 470, 1%, 0.1 W, AEC-Q200 Grade 0, 0402", Manufacturer=Panasonic, Power_W=100mW, Supplier Part Number 1=P470LCT-ND, TempCo="100 ppm/C", Tolerance_%=1%, Value2=0.1W, Value_Code=470R, ValueDisplayed=470
R9: library part CMP-0026754-1, "RES, 10.0 k, 1%, 0.063 W, AEC-Q200 Grade 0, 0402", Manufacturer="Stackpole Electronics Inc", PartNumber=RMCF0402FT10K0, Power_W=63mW, Supplier Part Number 1=RMCF0402FT10K0CT-ND, TempCo="100 ppm/C", Tolerance_%=1%, Value2=0.063W, Value_Code=10k0, ValueDisplayed=10.0k
R11 R12: library part CMP-0026729-1, "RES, 2.20 k, 1%, 0.063 W, 0402", Manufacturer="Yageo America", Power_W=63mW, Supplier Part Number 1=311-2.20KLRCT-ND, TempCo="100 ppm/C", Tolerance_%=1%, Value2=0.063W, Value_Code=2k20, ValueDisplayed=2.20k
R13 R14: library part CMP-0025874-3, "RES, 0, 5%, 0.1 W, 0603", Manufacturer=Panasonic, Power_W=100mW, Supplier Part Number 1=P0.0GCT-ND, TempCo="600 ppm/C", Tolerance_%=5%, Value2=0.1W, Value_Code=0000, ValueDisplayed=0
R15 R18: library part CMP-0026738-1, "RES, 49.9, 1%, 0.063 W, 0402", Manufacturer="Yageo America", Power_W=63mW, Supplier Part Number 1=311-49.9LRCT-ND, TempCo="100 ppm/C", Tolerance_%=1%, Value2=0.063W, Value_Code=49R9, ValueDisplayed=49.9
SH-J1 SH-J2: library part CMP-0003623-1, "Shunt, 100mil, Gold plated, Black", Alternate Manufacturer=3M, Alternate PartNumber=969102-0000-DA, Manufacturer=Samtec, Supplier Part Number 1=SNT-100-BK-G-ND
TP1: library part CMP-0055137-1, "Test Point, Miniature, Red, TH", Color=Red, Manufacturer=Keystone, PartNumber=5000, Supplier Part Number 1=36-5000-ND
TP2 TP3: library part CMP-0055138-1, "Test Point, Miniature, Black, TH", Color=Black, Manufacturer=Keystone, PartNumber=5001, Supplier Part Number 1=36-5001-ND
TP4 TP5 TP6 TP7 TP8 TP9 TP10 TP11 TP12 TP13 TP14 TP15 TP16 TP17 TP18: library part CMP-0055140-1, "Test Point, Miniature, Orange, TH", Color=Orange, Manufacturer=Keystone, PartNumber=5003, Supplier Part Number 1=36-5003-ND
U1 U2: library part CMP-0077820-2, "4.5 V to 26.4 V, Inductor-Less, Digital Input, Stereo, Closed-Loop Class-D Audio Amplifier with 96-kHz/192-kHz Extended Audio Processing, RHB0032N (VQFN-32)", Alternate Manufacturer="Texas Instruments", Alternate PartNumber=TAS5825MRHBT
U3: library part CMP-0005242-2, "EEPROM, 512KBIT, 400KHZ, 8TSSOP", Manufacturer=Microchip, Supplier Part Number 1=24LC512-I/ST-ND
U4 U5: library part CMP-0051026-1, "Single 2-Line to 1-Line Data Selector/Multiplexer, DCU0008A, LARGE T&R", F @ Nom Voltage(Max)(Mhz)=150, Generic Part Number=SN74LVC2G157, ICC @ Nom Voltage(Max)(mA)=0.01, Manufacturer="Texas Instruments", Operating Temperature Range(C)="-40 to 85", Rating=Catalog, tpd @ Nom Voltage(Max)(ns)=14,8,6,4, Voltage(Nom)(V)=1.8,2.5,3.3,5
ZZ1: library part CMP-0077236-1
ZZ2: library part CMP-0077237-1
ZZ3: library part CMP-0077238-1

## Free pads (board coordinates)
  round 7 hole 3.25: 0(9,35) 0(9,85)

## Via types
v1: diameter 0.508, hole 0.254, Top Layer to Bottom Layer, tented both sides, 343 vias
v2: diameter 0.635, hole 0.254, Top Layer to Bottom Layer, tented both sides, 130 vias
v3: diameter 0.508, hole 0.254, Top Layer to Bottom Layer, 14 vias
v4: diameter 0.5, hole 0.2, Top Layer to Bottom Layer, 10 vias
v5: diameter 0.762, hole 0.254, Top Layer to Bottom Layer, tented both sides, 8 vias
v6: diameter 6.5, hole 3.25, Top Layer to Bottom Layer, tented both sides, 4 vias

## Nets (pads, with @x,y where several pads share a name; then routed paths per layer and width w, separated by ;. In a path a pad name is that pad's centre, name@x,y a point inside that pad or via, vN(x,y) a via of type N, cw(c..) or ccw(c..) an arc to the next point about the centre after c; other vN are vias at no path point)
+3.3V: C7.1 C8.2 C11.2 C12.2 C45.2 J2.1 J3.1 J5.58 J5.60 J5.62 J5.64 R7.2 R8.2 R9.1 R11.2 R12.2 R19.1 TP1.1 U3.8 U4.8 U5.8 | length 114.1
  Top Layer w0.25: C7.1@13.962,57.784 14.062,57.884 v5(14.062,58.53)
  Top Layer w0.254: R8.2@6.604,53.474 6.604,52.375 6.979,52 v2(10.625,52) ; C7.1@13.962,57.784 13.975,57.771 13.975,56.5 ; U3.8@13.975,55.725 13.975,56.5 ; R9.1@16,57 15.5,57 15,56.5 13.975,56.5 ; R12.2@23.926,52.232 v5(24.926,52.232) ; R11.2@23.926,54.482 v5(25.02,54.482)
  Top Layer w0.5: v2(17.5,61.25) 17.5,63.75 v2(18.75,65) ; TP1.1@35,68.75 37.52,66.23 J2.1@47.5,66.23
  Signal Layer 2 w0.5: 14,54.75 14.062,54.812 v5(14.062,58.53) ; v5(24.926,52.232) 24.926,53.301 25.02,53.395 v5(25.02,54.482) ; v1(33.625,49.75) 34.375,50.5 34.375,51.75 v2(34.375,53.5) ; J3.1@47.5,53.77 J2.1@47.5,66.23
  Signal Layer 2 w0.75: 10.5,54.75 21.25,54.75 22.625,53.375 31.5,53.375 33.125,51.75 34.375,51.75
  Bottom Layer w0.2: R19.1@33.02,52.783 33.053,52.75 U4.8@34.5,52.75 ; U4.8@34.375,52.875 v2(34.375,53.5) ; v2@34.4,53.5 34.4,54.204 C8.2@34.552,54.356
  Bottom Layer w0.25: v1(33.625,49.75) C11.2@34.5,49.75 U5.8@34.5,48.75
  Bottom Layer w0.254: v2(10.625,52) 10.625,53.677 v2(10.922,53.974) ; R7.2@35,66.75 TP1.1@35,68.75
  Bottom Layer w0.5: 13.75,54.875 16.125,54.875 17.5,56.25 v2(17.5,61.25) ; v2(18.75,65) 27.5,65 31.25,68.75 TP1.1@35,68.75
  other v2: 10.875,55.5
  other v5: 10.086,54.339 10.086,55.214
\FAULT1: J5.22 R20.1 TP4.1 U1.9 | length 61.2
  Top Layer w0.2: v2(26.5,77.5) v2(26.5,81.25) ; R20.1@46.75,98 v2(47.625,98) 48.875,96.75 U1.9@52.6,96.75
  Bottom Layer w0.2: J5.22@12.086,71.271 15.771,71.271 19,74.5 26,74.5 26.5,75 v2(26.5,77.5) ; v2(26.5,81.25) 26.5,89 TP4.1@30,92.5 36.25,92.5 41.75,98 v2(47.625,98)
\FAULT2: J5.24 R3.1 TP5.1 U2.9 | length 91.7
  Top Layer w0.2: v2(13.75,70) 6.314,70 4.064,67.75 4.064,48.936 9.986,43.014 12.486,43.014 15,40.5 v2(25,40.5) ; R3.1@46.75,28 v2(47.625,28) 48.875,26.75 U2.9@52.6,26.75
  Bottom Layer w0.2: J5.24@12.086,70.636 13.114,70.636 v2(13.75,70) ; v2(25,40.5) 26.25,39.25 26.25,36.25 TP5.1@30,32.5 38.75,32.5 43.25,28 v2(47.625,28)
\MUTE1: J5.78 R21.1 TP14.1 U1.10 U4.2 U5.1 | length 110.7
  Top Layer w0.2: TP14.1@30,87.5 v2(40,87.5) ; v2(38.75,71.25) 40,72.5 v2(40,82.5) ; v2(40,57.5) 40,52.253 v1(40.005,52.248) ; R21.1@46.75,97.125 v2(47.625,97.125) 48.5,96.25 U1.10@52.6,96.25
  Top Layer w0.25: v2(15.625,50.625) v2(21.25,50.625) ; v2(33.125,54.375) 35.625,54.375 36.25,53.75 v2(36.25,51.744)
  Bottom Layer w0.2: TP14.1@30,87.5 33.75,91.25 36.875,91.25 42.75,97.125 v2(47.625,97.125) ; v2(38.75,71.25) 38.75,61.25 40,60 v2(40,57.5) ; v2(40,82.5) v2(40,87.5)
  Bottom Layer w0.25: J5.78@12.086,49.364 14.364,49.364 v2(15.625,50.625) ; v2(21.25,50.625) 24.375,50.625 28.125,54.375 v2(33.125,54.375)
  Bottom Layer w0.254: U5.1@37.5,48.75 36.5,48.75 36.25,49 v2(36.25,51.744) 36.756,52.25 40.003,52.25 v1(40.005,52.248)
\MUTE2: J5.98 R4.1 TP15.1 U2.10 U5.2 | length 82.7
  Top Layer w0.2: v2(40,40) 40,35 43.75,31.25 v2(45,31.25) ; R4.1@46.75,27.125 v2(47.625,27.125) 48.5,26.25 U2.10@52.6,26.25
  Bottom Layer w0.2: J5.98@12.086,43.014 13.736,43.014 15,41.75 15,37.5 17.5,35 20,35 22.5,32.5 25,32.5 26.25,31.25 26.25,28.75 27.5,27.5 TP15.1@30,27.5 31.75,25.75 43.25,25.75 44.625,27.125 v2(47.625,27.125) 48.5,27.125 49,27.625 49,29 46.75,31.25 v2(45,31.25) ; U5.2@37.6,48.25 38.6,48.25 40,46.85 v2(40,40)
\PDN1: J5.90 R23.1 TP18.1 U1.17 | length 77.4
  Top Layer w0.2: TP18.1@30,77.5 v2(38.75,77.5) ; R23.1@51,91.25 v2(51,92) 51.6,92.6 U1.17@53.25,92.6
  Top Layer w0.25: v2(15,45.554) 17.571,48.125 v2(18.75,48.125) ; v2(22.5,58.75) 22.5,70.625 v2(23.75,71.875) ; v2(26.875,73.125) 29.375,73.125 30,73.75 TP18.1@30,77.5
  Bottom Layer w0.2: J5.90@12.086,45.554 J5.90@12.086,45.57 ; v2(38.75,77.5) 41.25,77.5 42.5,78.75 42.5,83.5 v2(51,92)
  Bottom Layer w0.25: J5.90@12.086,45.554 v2(15,45.554) ; v2(18.75,48.125) 18.75,52.5 21.25,55 21.25,57.5 v2(22.5,58.75) ; v2(23.75,71.875) 25.625,71.875 v2(26.875,73.125)
\PDN2: J5.86 R6.1 TP17.1 U2.17 | length 75.5
  Top Layer w0.2: v2(23.75,33.75) 25,33.75 26.75,32 26.75,15.75 TP17.1@30,12.5 37.5,12.5 40,15 48.75,15 v2(50,16.25) ; R6.1@51,21.25 v2(51,22) 51.6,22.6 U2.17@53.25,22.6
  Bottom Layer w0.2: J5.86@12.086,46.824 15.676,46.824 16.25,46.25 16.25,43.75 23.75,36.25 v2(23.75,33.75) ; v2(50,16.25) 51,17.25 v2(51,22)
\WARN1: J5.34 R22.1 TP8.1 U1.11 | length 60.6
  Top Layer w0.2: v2(28.25,75) 28.25,80.75 TP8.1@30,82.5 ; R22.1@46.75,96.25 v2(47.625,96.25) 48.125,95.75 U1.11@52.6,95.75
  Bottom Layer w0.2: J5.34@12.086,67.461 26.961,67.461 28.25,68.75 v2(28.25,75) ; TP8.1@30,82.5 43.75,96.25 v2(47.625,96.25)
\WARN2: J5.28 R5.1 TP9.1 U2.11 | length 101.8
  Top Layer w0.2: v2(10.5,68.75) 5,63.25 5,50.5 10,45.5 12.5,45.5 15.5,42.5 v2(25,42.5) ; TP9.1@30,22.5 32.5,25 32.5,32.5 v2(30,35) ; v2(33.75,18.75) 45,18.75 v2(46.875,20.625) ; R5.1@46.75,26.25 v2(47.625,26.25) 48.125,25.75 U2.11@52.6,25.75
  Bottom Layer w0.2: v2(10.5,68.75) 11.116,69.366 J5.28@12.086,69.366 ; v2(25,42.5) 27.5,40 27.5,36.25 28.75,35 v2(30,35) ; TP9.1@30,22.5 v2(33.75,18.75) ; v2(46.875,20.625) 47.625,21.375 v2(47.625,26.25)
ADR1: R1.1 R17.1 U1.8 | length 8
  Top Layer w0.2: R1.1@46.75,99.75 R17.1@46.75,98.875 47.625,98.875 49.1,97.4 U1.8@53.25,97.4
ADR2: R2.1 R24.1 U2.8 | length 8
  Top Layer w0.2: R2.1@46.75,29.75 R24.1@46.75,28.875 47.625,28.875 49.1,27.4 U2.8@53.25,27.4
BST_A1+: C6.1 U1.1 | length 3.1
  Top Layer w0.2: U1.1@56.75,97.4 56.75,97.75 57.75,98.75 57.75,99.8 C6.1@57.95,100
BST_A1-: C9.1 U1.29 | length 3
  Top Layer w0.2: U1.29@57.4,95.25 59.8,95.25 C9.1@60.175,95.625 ; C9.1@60.237,95.562 C9.1@60.3,95.625
BST_A2+: C24.1 U2.1 | length 3.1
  Top Layer w0.25: U2.1@56.75,27.4 56.75,27.75 57.95,28.95 C24.1@57.95,30
BST_A2-: C27.1 U2.29 | length 3
  Top Layer w0.2: U2.29@57.4,25.25 59.8,25.25 C27.1@60.175,25.625 ; C27.1@60.237,25.562 C27.1@60.3,25.625
BST_B1+: C13.1 U1.24 | length 3.1
  Top Layer w0.2: U1.24@56.75,92.6 56.75,92.25 57.75,91.25 57.75,90.2 C13.1@57.95,90
BST_B1-: C10.1 U1.28 | length 3
  Top Layer w0.25: U1.28@57.4,94.75 59.8,94.75 C10.1@60.175,94.375 ; C10.1@60.237,94.438 C10.1@60.3,94.375
BST_B2+: C30.1 U2.24 | length 3.1
  Top Layer w0.25: U2.24@56.75,22.6 56.75,22.25 57.95,21.05 C30.1@57.95,20
BST_B2-: C28.1 U2.28 | length 2.9
  Top Layer w0.25: U2.28@57.4,24.75 59.8,24.75 C28.1@60.175,24.375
